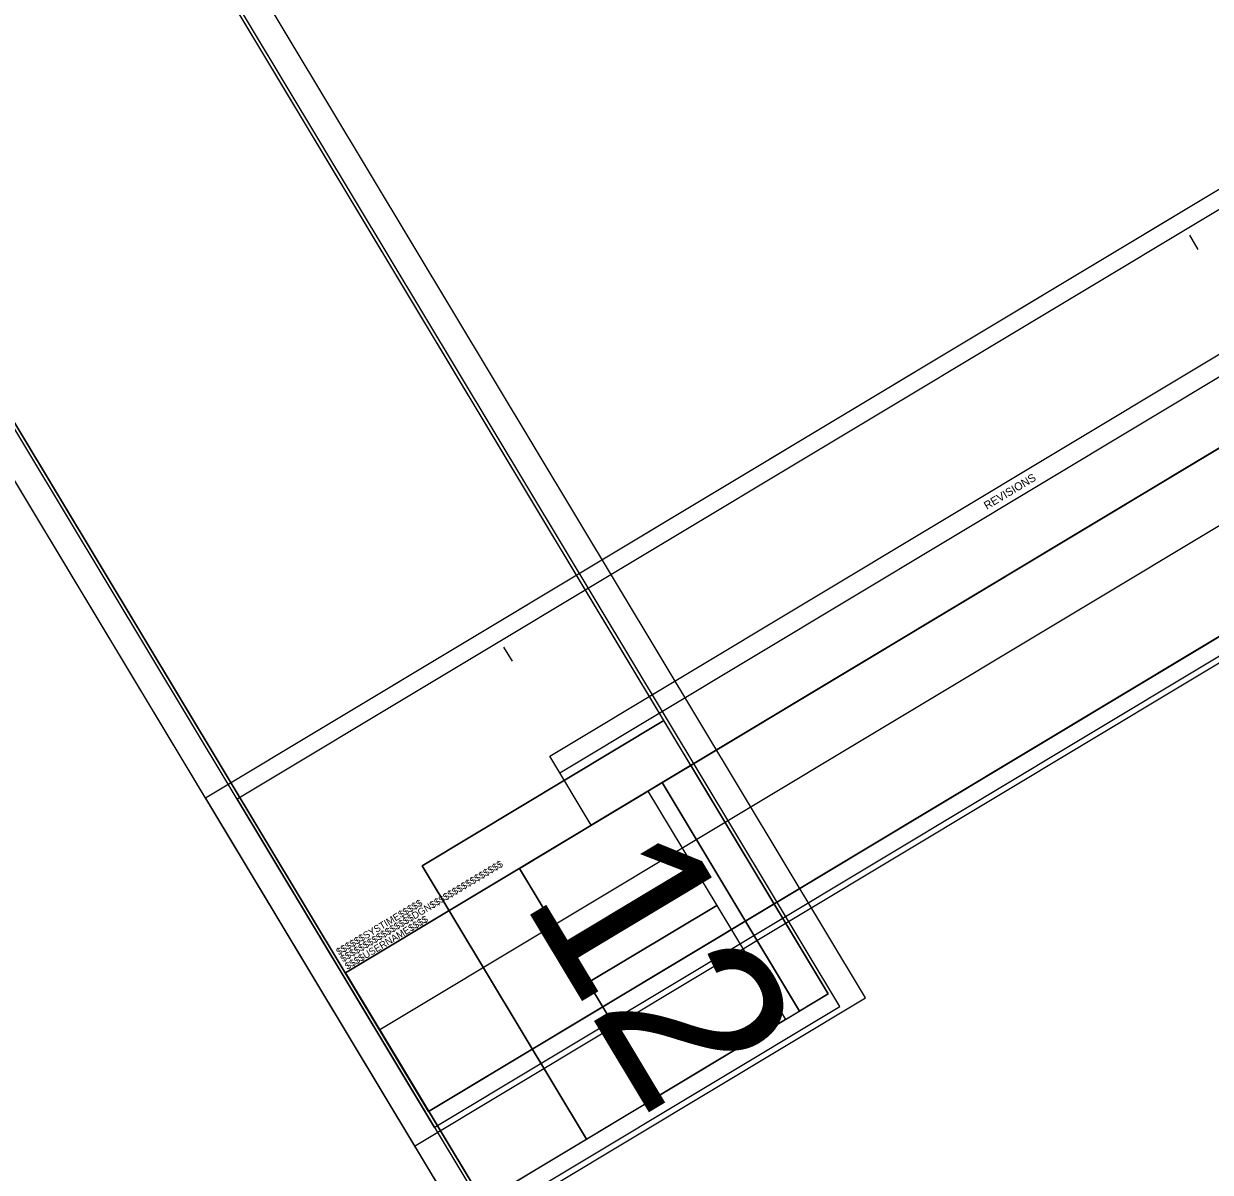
# Model space of a CAD drawing. Extents: x 1778994 to 1784559, y 810461 to 816654.
# Drawn here: x 1780168 to 1781058, y 814627 to 815489 of the extents above; entities that cross this region are included whole.
import ezdxf

# ---------------------------------------------------------------- set-up
doc = ezdxf.new("R2010")
doc.units = 0
for name, color, linetype in [('Sheet Block Revision CELL', 7, 'Continuous'), ('Sheet Clip Boundary CELL', 7, 'Continuous'), ('Sheet Cutting Line CELL', 7, 'Continuous'), ('Sheet Detail CELL', 7, 'Continuous'), ('Sheet Layout Plan Border', 7, 'Continuous'), ('Sheet Plan CELL', 7, 'Continuous'), ('Sheet Plan Layout CELL', 7, 'Continuous'), ('Sheet Plot Border Inside CELL', 7, 'Continuous'), ('Sheet Plot Border Outside CELL', 7, 'Continuous')]:
    doc.layers.add(name, color=color, linetype=linetype)

msp = doc.modelspace()

# ---------------------------------------------------------------- linework, layer by layer
at = {"layer": 'Sheet Block Revision CELL'}
msp.add_line((1780570.09, 814927.24), (1781247.79, 815334.46), dxfattribs=at)
msp.add_lwpolyline([(1780562.57, 814939.7), (1781240.29, 815346.92), (1781271.49, 815295.04), (1780593.77, 814887.83)], close=True, dxfattribs=at)
at = {"layer": 'Sheet Clip Boundary CELL'}
msp.add_lwpolyline([(1780435.23, 814734.24), (1781156.29, 813534.2), (1781875.03, 813966.07), (1781777.55, 814128.3), (1781958.83, 814237.22), (1781335.25, 815275.03)], close=True, dxfattribs=at)
at = {"layer": 'Sheet Cutting Line CELL'}
for p, q in [((1779594.06, 816089.98), (1780461.13, 814646.94)), ((1781243.03, 815472.18), (1780304.43, 814908.22)), ((1780304.43, 814908.22), (1781171.5, 813465.17))]:
    msp.add_line(p, q, dxfattribs=at)
at = {"layer": 'Sheet Layout Plan Border'}
msp.add_lwpolyline([(1780435.23, 814734.24), (1781156.29, 813534.2), (1781875.03, 813966.07), (1781777.55, 814128.3), (1781958.83, 814237.22), (1781335.25, 815275.03)], close=True, dxfattribs=at)
at = {"layer": 'Sheet Plan CELL'}
for p, q in [((1781042.28, 815330.57), (1781048.74, 815319.86)), ((1780528, 815021.54), (1780534.43, 815010.81)), ((1780646.97, 814919.85), (1780750.01, 814748.39)), ((1780646.97, 814919.85), (1780750.01, 814748.39)), ((1780539.85, 814855.47), (1780642.86, 814684)), ((1780409.47, 814777.1), (1780409.47, 814777.1))]:
    msp.add_line(p, q, dxfattribs=at)
for points in [[(1781371.71, 815213.87), (1780599.13, 816499.66), (1779699.11, 815958.87), (1780471.67, 814673.1)], [(1779699.11, 815958.87), (1780599.1, 816499.66), (1781268.67, 815385.38), (1781140.05, 815308.08), (1781243.07, 815136.61), (1780471.67, 814673.1)], [(1780771.51, 814761.26), (1779998.93, 816047.05), (1779098.9, 815506.26), (1779871.47, 814220.49)], [(1780409.47, 814777.1), (1781309.47, 815317.9), (1781979.04, 814203.61), (1781850.42, 814126.32), (1781953.44, 813954.84), (1781182.04, 813491.34)], [(1782082.08, 814032.11), (1781309.5, 815317.89), (1780409.47, 814777.1), (1781182.04, 813491.34)], [(1780668.47, 814932.77), (1780771.51, 814761.26), (1780750.01, 814748.39), (1780646.97, 814919.85)], [(1780636.26, 814913.42), (1780687.79, 814827.66), (1780591.35, 814769.71), (1780539.85, 814855.47)], [(1780687.79, 814827.66), (1780739.3, 814741.96), (1780642.86, 814684), (1780591.35, 814769.71)]]:
    msp.add_lwpolyline(points, close=True, dxfattribs=at)
at = {"layer": 'Sheet Plan Layout CELL'}
for points in [[(1780599.1, 816499.66), (1779699.11, 815958.87), (1780471.66, 814673.11), (1781190.41, 815104.98), (1781067.19, 815310.06), (1781248.47, 815418.98)], [(1779998.9, 816047.06), (1779098.9, 815506.26), (1779871.46, 814220.51), (1780590.21, 814652.37), (1780466.98, 814857.45), (1780648.26, 814966.37)], [(1781309.47, 815317.9), (1780409.47, 814777.1), (1781182.03, 813491.35), (1781900.78, 813923.22), (1781777.55, 814128.3), (1781958.83, 814237.22)], [(1780466.98, 814857.45), (1780590.22, 814652.35), (1780771.51, 814761.25), (1780648.26, 814966.37)]]:
    msp.add_lwpolyline(points, close=True, dxfattribs=at)
at = {"layer": 'Sheet Plot Border Inside CELL'}
for points in [[(1779617.9, 816089.14), (1780475.96, 814661.11), (1781380.26, 815204.46), (1780522.21, 816632.5)], [(1779017.7, 815636.53), (1779875.76, 814208.5), (1780780.06, 814751.85), (1779922.01, 816179.89)], [(1780328.27, 814907.37), (1781186.33, 813479.35), (1782090.63, 814022.7), (1781232.58, 815450.74)]]:
    msp.add_lwpolyline(points, close=True, dxfattribs=at)
at = {"layer": 'Sheet Plot Border Outside CELL'}
for points in [[(1779594.06, 816089.98), (1780461.13, 814646.94), (1781399.73, 815210.9), (1780532.66, 816653.94)], [(1778993.86, 815637.37), (1779860.93, 814194.33), (1780799.52, 814758.29), (1779932.46, 816201.34)], [(1780304.43, 814908.22), (1781171.5, 813465.17), (1782110.1, 814029.14), (1781243.03, 815472.18)]]:
    msp.add_lwpolyline(points, close=True, dxfattribs=at)

# ---------------------------------------------------------------- texts
at = {"layer": 'Sheet Block Revision CELL'}
msp.add_text('REVISIONS', height=6, rotation=31, dxfattribs=at).set_placement((1780890.42, 815124.45))
at = {"layer": 'Sheet Detail CELL'}
msp.add_text('TO PLOT FULL SIZE 62"X34"', height=75, rotation=51.63093, dxfattribs=at).set_placement((1780624.24, 813575.47))
at = {"layer": 'Sheet Plan CELL'}
for s, p in [('$$$$$$$$$$$$$$$$DGN$$$$$$$$$$$$$$$$', (1780407.57, 814784.87)), ('$$$$$$SYSTIME$$$$$', (1780404.42, 814790.06)), ('$$$$USERNAME$$$$', (1780410.95, 814779.26))]:
    msp.add_text(s, height=5.25, rotation=31, dxfattribs=at).set_placement(p)
at = {"layer": 'Sheet Plan Layout CELL'}
msp.add_text('12', height=131.25, rotation=301, dxfattribs=at).set_placement((1780540.96, 814832.21))

doc.saveas('drawing.dxf')
